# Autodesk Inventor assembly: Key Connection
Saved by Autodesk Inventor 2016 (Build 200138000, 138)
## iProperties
Created: 2015-03
Part Number: Key Connection
Document SubType Name: Assembly
Designer: Uglješa
ClientObjectVersion: 1
Author: Uglješa
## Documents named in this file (2)
- C:\Users\Ugljesa\Desktop\Turbokompr\Assembly1\Design Accelerator\Key Connection3.iam
- C:\Users\Uglješa\Documents\Inventor\Content Center Files\R2013\en-US\ISO 2491 - A\ISO 2491 - A  6 x 4 x 45.ipt
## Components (1 placed, 1 different names)
1. ISO 2491 A A  6 x 4 x 45:1
